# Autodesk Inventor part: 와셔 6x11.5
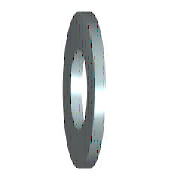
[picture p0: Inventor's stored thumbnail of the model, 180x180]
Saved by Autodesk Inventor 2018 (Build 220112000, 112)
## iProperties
IsCustomPart: 1
Created: 2012-02
Part Number: 와셔 6x11.5
Material: 강철, 연강
Description: 평면 와셔
Document SubType Name: Modeling
Standard: KS B 1326
Designer: mduedu
Standards Organization: KS
Language: ko-KR
Size Designation: 6x11.5
Categories: <MemberInstance><Categories><Category DisplayName="조임쇠" InternalName="e4da775c-781d-43d5-af7c-5136215cf5a6" Mnemonic="FSTN"><Category DisplayName="와셔" InternalN
Density: 1 g/cm^3
Appearance: 분홍색
Author: mduedu
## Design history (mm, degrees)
sketch "스케치"
  geometry: C1 r 5.75 at (0, 0); C2 r 3.2 at (0, 0); 1 further point
  constraints: 2 centre point, 2 coincident
  dimensions: "d0" = 6.4 diameter of C2 (= SD1); "d1" = 11.5 diameter of C1 (= SD2)
extrude "본체" new body sketch "스케치" distance "d2" = 1.6 (= SD); taper "d3" = 0 deg
workaxis "Work Axis1"
workplane "Work Plane1"
body "Solid1"
other parameters: "SD1" = 6.4 [user parameter; used in 1 equation term], "SD2" = 11.5 [user parameter; used in 1 equation term], "SD" = 1.6 [user parameter; used in 1 equation term], "d4" = 0, "d5" = 0, "d6" = 0, "d7" = 0, "NND" = 6 [user parameter]
